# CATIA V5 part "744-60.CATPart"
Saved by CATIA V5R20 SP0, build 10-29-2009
Part number: 744-60
Revision: TUTTO
Definition: NON CONOSCIUTO
Nomenclature: 744-60
Source: Unknown
Bounding box of the stored display mesh (mm): x -47.5 to 47.5, y -48 to 47.5, z -60 to 56
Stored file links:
  C:\Users\Utente\Desktop\IO LAVORO\3D X SITO CF\X SITO\744\744-60.CATPart
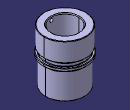
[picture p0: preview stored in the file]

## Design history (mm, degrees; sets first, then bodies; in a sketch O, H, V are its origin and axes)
Body1 "744-60 sol1" (main body)
  Solid1: solid without history
Body2 "IDV1M8_Ingrassatore-1"
  Solid2: solid without history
